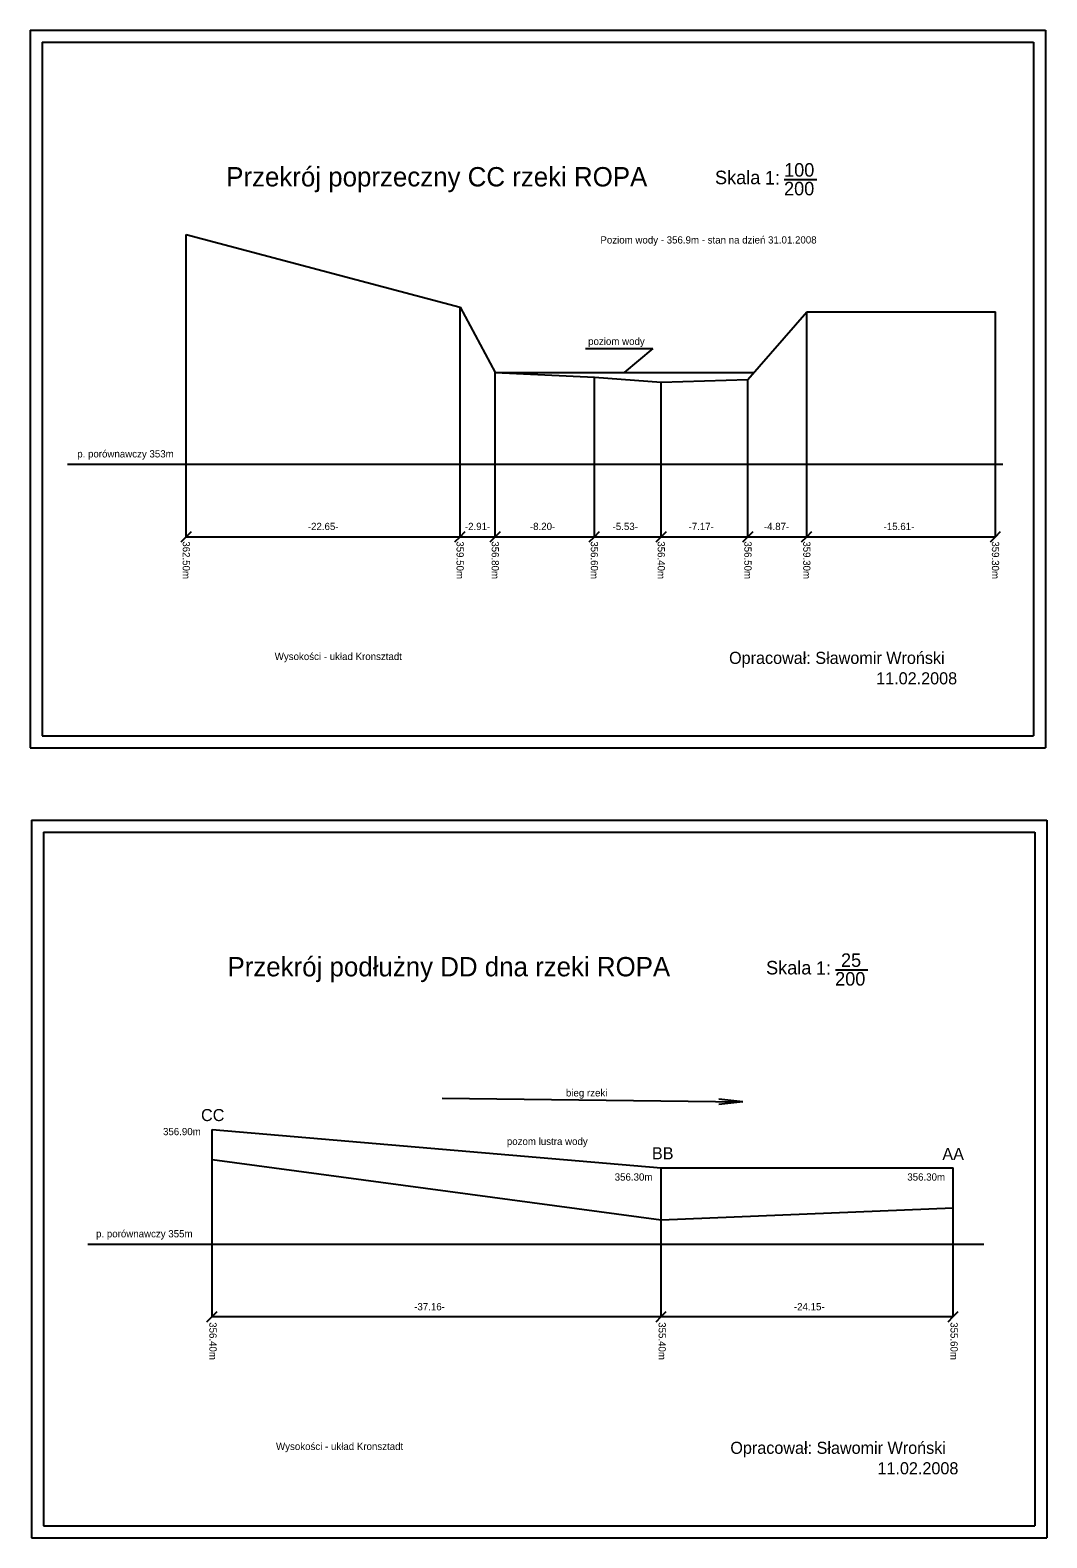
# Model space of a CAD drawing. Extents: x 746 to 788, y 74 to 202.
# Drawn here: x 745.5 to 787.6, y 74.2 to 136.6 of the extents above; entities that cross this region are included whole.
import ezdxf

# ---------------------------------------------------------------- set-up
doc = ezdxf.new("R2010")
doc.units = 0
doc.layers.add('Default', color=7, linetype='Continuous')
doc.layers.add('siatka', color=7, linetype='Continuous')

msp = doc.modelspace()

# ---------------------------------------------------------------- linework, layer by layer
at = {"layer": 'Default'}
for p, q in [((745.545, 136.555), (787.545, 136.555)), ((745.545, 136.555), (745.545, 106.855)), ((746.045, 136.055), (787.045, 136.055)), ((746.045, 136.055), (746.045, 107.355)), ((787.045, 136.055), (787.045, 107.355)), ((787.545, 136.555), (787.545, 106.855)), ((776.74, 130.377), (778.081, 130.377)), ((752.004, 115.593), (752.004, 128.093)), ((752.004, 128.093), (763.329, 125.093)), ((763.329, 115.593), (763.329, 125.093)), ((763.329, 125.093), (764.784, 122.393)), ((775.234, 122.093), (777.669, 124.893)), ((777.669, 115.593), (777.669, 124.893)), ((777.669, 124.893), (785.474, 124.893)), ((785.474, 115.593), (785.474, 124.893)), ((768.517, 123.388), (771.295, 123.388)), ((771.295, 123.388), (770.116, 122.393)), ((764.784, 122.393), (775.495, 122.393)), ((764.784, 115.593), (764.784, 122.393)), ((764.784, 122.393), (768.884, 122.193)), ((768.884, 115.593), (768.884, 122.193)), ((768.884, 122.193), (771.649, 121.993)), ((771.649, 121.993), (775.234, 122.093)), ((771.649, 115.593), (771.649, 121.993)), ((775.234, 115.593), (775.234, 122.093)), ((751.792, 115.38), (752.004, 115.593)), ((752.004, 115.593), (752.217, 115.805)), ((763.117, 115.38), (763.329, 115.593)), ((763.329, 115.593), (763.542, 115.805)), ((764.572, 115.38), (764.784, 115.593)), ((764.784, 115.593), (764.997, 115.805)), ((768.672, 115.38), (768.884, 115.593)), ((768.884, 115.593), (769.097, 115.805)), ((771.437, 115.38), (771.649, 115.593)), ((771.649, 115.593), (771.862, 115.805)), ((775.022, 115.38), (775.234, 115.593)), ((775.234, 115.593), (775.447, 115.805)), ((777.457, 115.38), (777.669, 115.593)), ((777.669, 115.593), (777.882, 115.805)), ((785.262, 115.38), (785.474, 115.593)), ((785.474, 115.593), (785.687, 115.805)), ((746.045, 107.355), (787.045, 107.355)), ((745.545, 106.855), (787.545, 106.855)), ((745.598, 103.868), (787.598, 103.868)), ((745.598, 103.868), (745.598, 74.168)), ((787.598, 103.868), (787.598, 74.168)), ((746.098, 103.368), (787.098, 103.368)), ((746.098, 103.368), (746.098, 74.668)), ((787.098, 103.368), (787.098, 74.668)), ((778.853, 97.677), (780.193, 97.677)), ((762.582, 92.364), (775.022, 92.209)), ((775.022, 92.209), (774.034, 92.099)), ((775.022, 92.209), (774.035, 92.322)), ((753.067, 89.821), (753.067, 91.071)), ((753.067, 91.071), (771.647, 89.481)), ((753.067, 83.321), (753.067, 89.821)), ((753.067, 89.821), (771.647, 87.321)), ((771.647, 87.321), (771.647, 89.481)), ((771.647, 89.481), (783.722, 89.481)), ((783.722, 87.821), (783.722, 89.481)), ((771.647, 87.321), (783.722, 87.821)), ((783.722, 83.321), (783.722, 87.821)), ((771.647, 83.321), (771.647, 87.321)), ((752.855, 83.109), (753.067, 83.321)), ((753.067, 83.321), (753.279, 83.533)), ((771.435, 83.109), (771.647, 83.321)), ((771.647, 83.321), (771.859, 83.533)), ((783.51, 83.109), (783.722, 83.321)), ((783.722, 83.321), (783.934, 83.533)), ((746.098, 74.668), (787.098, 74.668)), ((745.598, 74.168), (787.598, 74.168))]:
    msp.add_line(p, q, dxfattribs=at)
at = {"layer": 'siatka'}
for p, q in [((747.092, 118.593), (785.782, 118.593)), ((752.004, 115.593), (785.474, 115.593)), ((747.93, 86.321), (784.996, 86.321)), ((753.067, 83.321), (783.722, 83.321))]:
    msp.add_line(p, q, dxfattribs=at)

# ---------------------------------------------------------------- texts
at = {"layer": 'Default'}
for s, height, p in [('100', 0.56, (776.731, 130.493)), ('Przekrój poprzeczny CC rzeki ROPA', 0.8, (753.654, 130.089)), ('Skala', 0.56, (773.873, 130.181)), ('1:', 0.56, (775.933, 130.168)), ('200', 0.56, (776.728, 129.72)), ('Poziom wody - 356.9m - stan na dzień 31.01.2008', 0.3, (769.132, 127.726)), ('poziom wody', 0.3, (768.625, 123.53)), ('p. porównawczy 353m', 0.3, (747.492, 118.874)), ('-22.65-', 0.3, (757.03, 115.87)), ('-2.91-', 0.3, (763.527, 115.87)), ('-8.20-', 0.3, (766.217, 115.87)), ('-5.53-', 0.3, (769.637, 115.87)), ('-7.17-', 0.3, (772.778, 115.87)), ('-4.87-', 0.3, (775.895, 115.87)), ('-15.61-', 0.3, (780.846, 115.87)), ('Wysokości - układ Kronsztadt', 0.3, (755.661, 110.49)), ('Opracował: Sławomir Wroński', 0.5, (774.454, 110.331)), ('11.02.2008', 0.5, (780.541, 109.485)), ('Przekrój podłużny DD dna rzeki ROPA', 0.8, (753.707, 97.402)), ('Skala', 0.56, (775.985, 97.481)), ('1:', 0.56, (778.045, 97.469)), ('25', 0.56, (779.083, 97.793)), ('200', 0.56, (778.841, 97.02)), ('bieg rzeki', 0.3, (767.706, 92.432)), ('CC', 0.5, (752.613, 91.413)), ('356.90m', 0.3, (751.04, 90.83)), ('pozom lustra wody', 0.3, (765.263, 90.424)), ('BB', 0.5, (771.265, 89.832)), ('AA', 0.5, (783.277, 89.803)), ('356.30m', 0.3, (769.724, 88.95)), ('356.30m', 0.3, (781.827, 88.95)), ('p. porównawczy 355m', 0.3, (748.272, 86.602)), ('-37.16-', 0.3, (761.43, 83.583)), ('-24.15-', 0.3, (777.136, 83.583)), ('Wysokości - układ Kronsztadt', 0.3, (755.714, 77.803)), ('Opracował: Sławomir Wroński', 0.5, (774.507, 77.644)), ('11.02.2008', 0.5, (780.593, 76.798))]:
    msp.add_text(s, height=height, dxfattribs=at).set_placement(p)
for s, p in [('362.50m', (751.855, 115.404)), ('359.50m', (763.18, 115.404)), ('356.80m', (764.635, 115.404)), ('356.60m', (768.735, 115.404)), ('356.40m', (771.5, 115.404)), ('356.50m', (775.085, 115.404)), ('359.30m', (777.52, 115.404)), ('359.30m', (785.325, 115.404)), ('356.40m', (752.958, 83.091)), ('355.40m', (771.538, 83.091)), ('355.60m', (783.613, 83.091))]:
    msp.add_text(s, height=0.3, rotation=270, dxfattribs=at).set_placement(p)

doc.saveas('drawing.dxf')
